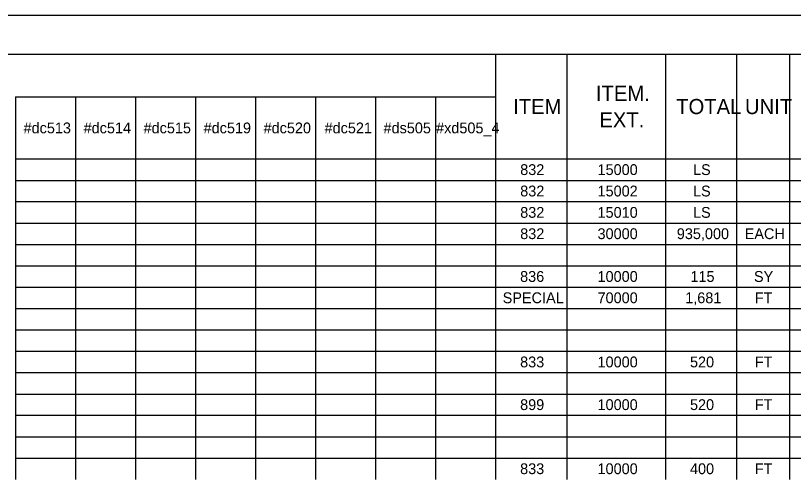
# Model space of a CAD drawing. Extents: x 0.2 to 34.2, y 0 to 22.
# Drawn here: x 13.45 to 23.52, y 16.02 to 22.03 of the extents above; entities that cross this region are included whole.
import ezdxf

# ---------------------------------------------------------------- set-up
doc = ezdxf.new("R2010")
doc.units = 0
for name, color, linetype in [('Default', 7, 'Continuous'), ('SH_Border', 7, 'Continuous'), ('SH_Cut_Line', 7, 'Continuous')]:
    doc.layers.add(name, color=color, linetype=linetype)

msp = doc.modelspace()

# ---------------------------------------------------------------- linework, layer by layer
at = {"layer": 'Default'}
for p, q in [((13.445, 21.525), (14.223, 21.525)), ((14.223, 21.525), (16.555, 21.525)), ((16.555, 21.525), (32.196, 21.525)), ((19.665, 21.525), (19.665, 21.249)), ((20.587, 21.525), (20.587, 21.249)), ((21.865, 21.525), (21.865, 21.249)), ((22.788, 21.525), (22.788, 21.249)), ((23.473, 21.525), (23.473, 21.249)), ((19.665, 21.249), (19.665, 20.972)), ((20.587, 21.249), (20.587, 20.972)), ((21.865, 21.249), (21.865, 20.972)), ((22.788, 21.249), (22.788, 20.972)), ((23.473, 21.249), (23.473, 20.972)), ((13.445, 20.972), (14.223, 20.972)), ((13.445, 20.972), (13.445, 20.722)), ((14.223, 20.972), (16.555, 20.972)), ((14.223, 20.972), (14.223, 20.722)), ((15, 20.972), (15, 20.722)), ((15.778, 20.972), (15.778, 20.722)), ((16.555, 20.972), (19.665, 20.972)), ((16.555, 20.972), (16.555, 20.722)), ((17.332, 20.972), (17.332, 20.722)), ((18.11, 20.972), (18.11, 20.722)), ((18.887, 20.972), (18.887, 20.722)), ((19.665, 20.972), (19.665, 20.722)), ((20.587, 20.972), (20.587, 20.722)), ((21.865, 20.972), (21.865, 20.722)), ((22.788, 20.972), (22.788, 20.722)), ((23.473, 20.972), (23.473, 20.722)), ((13.445, 20.722), (13.445, 20.445)), ((14.223, 20.722), (14.223, 20.445)), ((15, 20.722), (15, 20.445)), ((15.778, 20.722), (15.778, 20.445)), ((16.555, 20.722), (16.555, 20.445)), ((17.332, 20.722), (17.332, 20.445)), ((18.11, 20.722), (18.11, 20.445)), ((18.887, 20.722), (18.887, 20.445)), ((19.665, 20.722), (19.665, 20.445)), ((20.587, 20.722), (20.587, 20.445)), ((21.865, 20.722), (21.865, 20.445)), ((22.788, 20.722), (22.788, 20.445)), ((23.473, 20.722), (23.473, 20.445)), ((13.445, 20.445), (13.445, 20.168)), ((14.223, 20.445), (14.223, 20.168)), ((15, 20.445), (15, 20.168)), ((15.778, 20.445), (15.778, 20.168)), ((16.555, 20.445), (16.555, 20.168)), ((17.332, 20.445), (17.332, 20.168)), ((18.11, 20.445), (18.11, 20.168)), ((18.887, 20.445), (18.887, 20.168)), ((19.665, 20.445), (19.665, 20.168)), ((20.587, 20.445), (20.587, 20.168)), ((21.865, 20.445), (21.865, 20.168)), ((22.788, 20.445), (22.788, 20.168)), ((23.473, 20.445), (23.473, 20.168)), ((13.445, 20.168), (14.223, 20.168)), ((13.445, 20.168), (13.445, 19.891)), ((14.223, 20.168), (16.555, 20.168)), ((14.223, 20.168), (14.223, 19.891)), ((15, 20.168), (15, 19.891)), ((15.778, 20.168), (15.778, 19.891)), ((16.555, 20.168), (32.196, 20.168)), ((16.555, 20.168), (16.555, 19.891)), ((17.332, 20.168), (17.332, 19.891)), ((18.11, 20.168), (18.11, 19.891)), ((18.887, 20.168), (18.887, 19.891)), ((19.665, 20.168), (19.665, 19.891)), ((20.587, 20.168), (20.587, 19.891)), ((21.865, 20.168), (21.865, 19.891)), ((22.788, 20.168), (22.788, 19.891)), ((23.473, 20.168), (23.473, 19.891)), ((13.445, 19.891), (14.223, 19.891)), ((13.445, 19.891), (13.445, 19.615)), ((14.223, 19.891), (16.555, 19.891)), ((14.223, 19.891), (14.223, 19.615)), ((15, 19.891), (15, 19.615)), ((15.778, 19.891), (15.778, 19.615)), ((16.555, 19.891), (32.196, 19.891)), ((16.555, 19.891), (16.555, 19.615)), ((17.332, 19.891), (17.332, 19.615)), ((18.11, 19.891), (18.11, 19.615)), ((18.887, 19.891), (18.887, 19.615)), ((19.665, 19.891), (19.665, 19.615)), ((20.587, 19.891), (20.587, 19.615)), ((21.865, 19.891), (21.865, 19.615)), ((22.788, 19.891), (22.788, 19.615)), ((23.473, 19.891), (23.473, 19.615)), ((13.445, 19.615), (14.223, 19.615)), ((13.445, 19.615), (13.445, 19.338)), ((14.223, 19.615), (16.555, 19.615)), ((14.223, 19.615), (14.223, 19.338)), ((15, 19.615), (15, 19.338)), ((15.778, 19.615), (15.778, 19.338)), ((16.555, 19.615), (32.196, 19.615)), ((16.555, 19.615), (16.555, 19.338)), ((17.332, 19.615), (17.332, 19.338)), ((18.11, 19.615), (18.11, 19.338)), ((18.887, 19.615), (18.887, 19.338)), ((19.665, 19.615), (19.665, 19.338)), ((20.587, 19.615), (20.587, 19.338)), ((21.865, 19.615), (21.865, 19.338)), ((22.788, 19.615), (22.788, 19.338)), ((23.473, 19.615), (23.473, 19.338)), ((13.445, 19.338), (14.223, 19.338)), ((13.445, 19.338), (13.445, 19.061)), ((14.223, 19.338), (16.555, 19.338)), ((14.223, 19.338), (14.223, 19.061)), ((15, 19.338), (15, 19.061)), ((15.778, 19.338), (15.778, 19.061)), ((16.555, 19.338), (32.196, 19.338)), ((16.555, 19.338), (16.555, 19.061)), ((17.332, 19.338), (17.332, 19.061)), ((18.11, 19.338), (18.11, 19.061)), ((18.887, 19.338), (18.887, 19.061)), ((19.665, 19.338), (19.665, 19.061)), ((20.587, 19.338), (20.587, 19.061)), ((21.865, 19.338), (21.865, 19.061)), ((22.788, 19.338), (22.788, 19.061)), ((23.473, 19.338), (23.473, 19.061)), ((13.445, 19.061), (14.223, 19.061)), ((13.445, 19.061), (13.445, 18.785)), ((14.223, 19.061), (16.555, 19.061)), ((14.223, 19.061), (14.223, 18.785)), ((15, 19.061), (15, 18.785)), ((15.778, 19.061), (15.778, 18.785)), ((16.555, 19.061), (32.196, 19.061)), ((16.555, 19.061), (16.555, 18.785)), ((17.332, 19.061), (17.332, 18.785)), ((18.11, 19.061), (18.11, 18.785)), ((18.887, 19.061), (18.887, 18.785)), ((19.665, 19.061), (19.665, 18.785)), ((20.587, 19.061), (20.587, 18.785)), ((21.865, 19.061), (21.865, 18.785)), ((22.788, 19.061), (22.788, 18.785)), ((23.473, 19.061), (23.473, 18.785)), ((13.445, 18.785), (14.223, 18.785)), ((13.445, 18.785), (13.445, 18.508)), ((14.223, 18.785), (16.555, 18.785)), ((14.223, 18.785), (14.223, 18.508)), ((15, 18.785), (15, 18.508)), ((15.778, 18.785), (15.778, 18.508)), ((16.555, 18.785), (32.196, 18.785)), ((16.555, 18.785), (16.555, 18.508)), ((17.332, 18.785), (17.332, 18.508)), ((18.11, 18.785), (18.11, 18.508)), ((18.887, 18.785), (18.887, 18.508)), ((19.665, 18.785), (19.665, 18.508)), ((20.587, 18.785), (20.587, 18.508)), ((21.865, 18.785), (21.865, 18.508)), ((22.788, 18.785), (22.788, 18.508)), ((23.473, 18.785), (23.473, 18.508)), ((13.445, 18.508), (14.223, 18.508)), ((13.445, 18.508), (13.445, 18.231)), ((14.223, 18.508), (16.555, 18.508)), ((14.223, 18.508), (14.223, 18.231)), ((15, 18.508), (15, 18.231)), ((15.778, 18.508), (15.778, 18.231)), ((16.555, 18.508), (32.196, 18.508)), ((16.555, 18.508), (16.555, 18.231)), ((17.332, 18.508), (17.332, 18.231)), ((18.11, 18.508), (18.11, 18.231)), ((18.887, 18.508), (18.887, 18.231)), ((19.665, 18.508), (19.665, 18.231)), ((20.587, 18.508), (20.587, 18.231)), ((21.865, 18.508), (21.865, 18.231)), ((22.788, 18.508), (22.788, 18.231)), ((23.473, 18.508), (23.473, 18.231)), ((13.445, 18.231), (14.223, 18.231)), ((13.445, 18.231), (13.445, 17.954)), ((14.223, 18.231), (16.555, 18.231)), ((14.223, 18.231), (14.223, 17.954)), ((15, 18.231), (15, 17.954)), ((15.778, 18.231), (15.778, 17.954)), ((16.555, 18.231), (32.196, 18.231)), ((16.555, 18.231), (16.555, 17.954)), ((17.332, 18.231), (17.332, 17.954)), ((18.11, 18.231), (18.11, 17.954)), ((18.887, 18.231), (18.887, 17.954)), ((19.665, 18.231), (19.665, 17.954)), ((20.587, 18.231), (20.587, 17.954)), ((21.865, 18.231), (21.865, 17.954)), ((22.788, 18.231), (22.788, 17.954)), ((23.473, 18.231), (23.473, 17.954)), ((13.445, 17.954), (14.223, 17.954)), ((13.445, 17.954), (13.445, 17.678)), ((14.223, 17.954), (16.555, 17.954)), ((14.223, 17.954), (14.223, 17.678)), ((15, 17.954), (15, 17.678)), ((15.778, 17.954), (15.778, 17.678)), ((16.555, 17.954), (32.196, 17.954)), ((16.555, 17.954), (16.555, 17.678)), ((17.332, 17.954), (17.332, 17.678)), ((18.11, 17.954), (18.11, 17.678)), ((18.887, 17.954), (18.887, 17.678)), ((19.665, 17.954), (19.665, 17.678)), ((20.587, 17.954), (20.587, 17.678)), ((21.865, 17.954), (21.865, 17.678)), ((22.788, 17.954), (22.788, 17.678)), ((23.473, 17.954), (23.473, 17.678)), ((13.445, 17.678), (14.223, 17.678)), ((13.445, 17.678), (13.445, 17.401)), ((14.223, 17.678), (16.555, 17.678)), ((14.223, 17.678), (14.223, 17.401)), ((15, 17.678), (15, 17.401)), ((15.778, 17.678), (15.778, 17.401)), ((16.555, 17.678), (32.196, 17.678)), ((16.555, 17.678), (16.555, 17.401)), ((17.332, 17.678), (17.332, 17.401)), ((18.11, 17.678), (18.11, 17.401)), ((18.887, 17.678), (18.887, 17.401)), ((19.665, 17.678), (19.665, 17.401)), ((20.587, 17.678), (20.587, 17.401)), ((21.865, 17.678), (21.865, 17.401)), ((22.788, 17.678), (22.788, 17.401)), ((23.473, 17.678), (23.473, 17.401)), ((13.445, 17.401), (14.223, 17.401)), ((13.445, 17.401), (13.445, 17.124)), ((14.223, 17.401), (16.555, 17.401)), ((14.223, 17.401), (14.223, 17.124)), ((15, 17.401), (15, 17.124)), ((15.778, 17.401), (15.778, 17.124)), ((16.555, 17.401), (32.196, 17.401)), ((16.555, 17.401), (16.555, 17.124)), ((17.332, 17.401), (17.332, 17.124)), ((18.11, 17.401), (18.11, 17.124)), ((18.887, 17.401), (18.887, 17.124)), ((19.665, 17.401), (19.665, 17.124)), ((20.587, 17.401), (20.587, 17.124)), ((21.865, 17.401), (21.865, 17.124)), ((22.788, 17.401), (22.788, 17.124)), ((23.473, 17.401), (23.473, 17.124)), ((13.445, 17.124), (14.223, 17.124)), ((13.445, 17.124), (13.445, 16.848)), ((14.223, 17.124), (16.555, 17.124)), ((14.223, 17.124), (14.223, 16.848)), ((15, 17.124), (15, 16.848)), ((15.778, 17.124), (15.778, 16.848)), ((16.555, 17.124), (32.196, 17.124)), ((16.555, 17.124), (16.555, 16.848)), ((17.332, 17.124), (17.332, 16.848)), ((18.11, 17.124), (18.11, 16.848)), ((18.887, 17.124), (18.887, 16.848)), ((19.665, 17.124), (19.665, 16.848)), ((20.587, 17.124), (20.587, 16.848)), ((21.865, 17.124), (21.865, 16.848)), ((22.788, 17.124), (22.788, 16.848)), ((23.473, 17.124), (23.473, 16.848)), ((13.445, 16.848), (14.223, 16.848)), ((13.445, 16.848), (13.445, 16.571)), ((14.223, 16.848), (16.555, 16.848)), ((14.223, 16.848), (14.223, 16.571)), ((15, 16.848), (15, 16.571)), ((15.778, 16.848), (15.778, 16.571)), ((16.555, 16.848), (32.196, 16.848)), ((16.555, 16.848), (16.555, 16.571)), ((17.332, 16.848), (17.332, 16.571)), ((18.11, 16.848), (18.11, 16.571)), ((18.887, 16.848), (18.887, 16.571)), ((19.665, 16.848), (19.665, 16.571)), ((20.587, 16.848), (20.587, 16.571)), ((21.865, 16.848), (21.865, 16.571)), ((22.788, 16.848), (22.788, 16.571)), ((23.473, 16.848), (23.473, 16.571)), ((13.445, 16.571), (14.223, 16.571)), ((13.445, 16.571), (13.445, 16.294)), ((14.223, 16.571), (16.555, 16.571)), ((14.223, 16.571), (14.223, 16.294)), ((15, 16.571), (15, 16.294)), ((15.778, 16.571), (15.778, 16.294)), ((16.555, 16.571), (32.196, 16.571)), ((16.555, 16.571), (16.555, 16.294)), ((17.332, 16.571), (17.332, 16.294)), ((18.11, 16.571), (18.11, 16.294)), ((18.887, 16.571), (18.887, 16.294)), ((19.665, 16.571), (19.665, 16.294)), ((20.587, 16.571), (20.587, 16.294)), ((21.865, 16.571), (21.865, 16.294)), ((22.788, 16.571), (22.788, 16.294)), ((23.473, 16.571), (23.473, 16.294)), ((13.445, 16.294), (14.223, 16.294)), ((13.445, 16.294), (13.445, 16.018)), ((14.223, 16.294), (16.555, 16.294)), ((14.223, 16.294), (14.223, 16.018)), ((15, 16.294), (15, 16.018)), ((15.778, 16.294), (15.778, 16.018)), ((16.555, 16.294), (32.196, 16.294)), ((16.555, 16.294), (16.555, 16.018)), ((17.332, 16.294), (17.332, 16.018)), ((18.11, 16.294), (18.11, 16.018)), ((18.887, 16.294), (18.887, 16.018)), ((19.665, 16.294), (19.665, 16.018)), ((20.587, 16.294), (20.587, 16.018)), ((21.865, 16.294), (21.865, 16.018)), ((22.788, 16.294), (22.788, 16.018)), ((23.473, 16.294), (23.473, 16.018))]:
    msp.add_line(p, q, dxfattribs=at)
at = {"layer": 'SH_Border'}
msp.add_lwpolyline([(1.692, 21.525), (33.692, 21.525), (33.692, 0.525), (1.692, 0.525)], close=True, dxfattribs=at)
at = {"layer": 'SH_Cut_Line'}
msp.add_lwpolyline([(0.192, 0.025), (34.192, 0.025), (34.192, 22.025), (0.192, 22.025)], close=True, dxfattribs=at)

# ---------------------------------------------------------------- texts
at = {"layer": 'Default'}
for s, height, p in [('ITEM.', 0.196, (20.965, 20.92)), ('ITEM', 0.196, (19.892, 20.749)), ('TOTAL', 0.196, (22.005, 20.749)), ('UNIT', 0.196, (22.896, 20.749)), ('EXT.', 0.196, (21.01, 20.577)), ('#dc513', 0.14, (13.549, 20.5)), ('#dc514', 0.14, (14.327, 20.5)), ('#dc515', 0.14, (15.104, 20.5)), ('#dc519', 0.14, (15.882, 20.5)), ('#dc520', 0.14, (16.659, 20.5)), ('#dc521', 0.14, (17.449, 20.5)), ('#ds505', 0.14, (18.213, 20.5)), ('#xd505_4', 0.14, (18.894, 20.5)), ('832', 0.14, (19.984, 19.96)), ('15000', 0.14, (20.986, 19.96)), ('LS', 0.14, (22.223, 19.96)), ('832', 0.14, (19.984, 19.683)), ('15002', 0.14, (20.986, 19.683)), ('LS', 0.14, (22.223, 19.683)), ('832', 0.14, (19.984, 19.406)), ('15010', 0.14, (20.986, 19.406)), ('LS', 0.14, (22.223, 19.406)), ('832', 0.14, (19.984, 19.13)), ('30000', 0.14, (20.986, 19.13)), ('935,000', 0.14, (22.013, 19.13)), ('EACH', 0.14, (22.893, 19.13)), ('836', 0.14, (19.983, 18.576)), ('10000', 0.14, (20.986, 18.576)), ('115', 0.14, (22.19, 18.576)), ('SY', 0.14, (23.013, 18.576)), ('SPECIAL', 0.14, (19.757, 18.3)), ('70000', 0.14, (20.986, 18.3)), ('1,681', 0.14, (22.122, 18.3)), ('FT', 0.14, (23.024, 18.3)), ('833', 0.14, (19.983, 17.469)), ('10000', 0.14, (20.986, 17.469)), ('520', 0.14, (22.184, 17.469)), ('FT', 0.14, (23.024, 17.469)), ('899', 0.14, (19.983, 16.916)), ('10000', 0.14, (20.986, 16.916)), ('520', 0.14, (22.184, 16.916)), ('FT', 0.14, (23.024, 16.916)), ('833', 0.14, (19.983, 16.086)), ('10000', 0.14, (20.986, 16.086)), ('400', 0.14, (22.184, 16.086)), ('FT', 0.14, (23.024, 16.086))]:
    msp.add_text(s, height=height, dxfattribs=at).set_placement(p)

doc.saveas('drawing.dxf')
